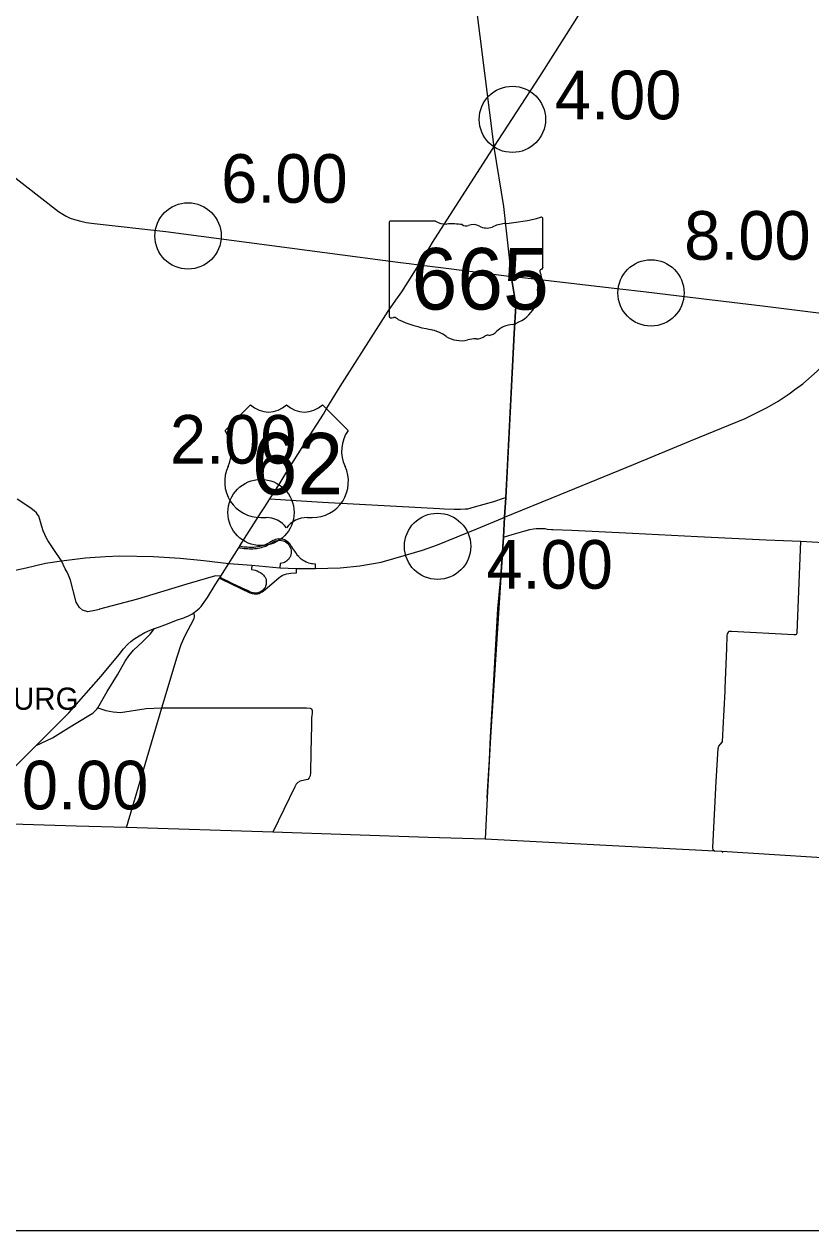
# Model space of a CAD drawing. Extents: x 1659811 to 1934326, y 644115 to 934867.
# Drawn here: x 1783780 to 1801590, y 650175 to 677476 of the extents above; entities that cross this region are included whole.
import ezdxf

# ---------------------------------------------------------------- set-up
doc = ezdxf.new("R2010")
doc.units = 0
for name, color, linetype in [('Default', 7, 'Continuous'), ('GM_X_Corporation_Text', 7, 'Continuous'), ('GM_X_County', 7, 'Continuous'), ('GM_X_County_Road', 7, 'Continuous'), ('GM_X_Interchange_Ramps', 7, 'Continuous'), ('GM_X_Interstate_Route', 7, 'Continuous'), ('GM_X_State_Route', 7, 'Continuous'), ('GM_X_State_Shield', 7, 'Continuous'), ('GM_X_Township', 7, 'Continuous'), ('GM_X_Township_Road', 7, 'Continuous'), ('GM_X_US_Route', 7, 'Continuous'), ('GM_X_US_Shield', 7, 'Continuous'), ('SC_Scratch1', 7, 'Continuous')]:
    doc.layers.add(name, color=color, linetype=linetype)

msp = doc.modelspace()

# ---------------------------------------------------------------- linework, layer by layer
at = {"layer": 'Default'}
for centre in [(1794833, 675322), (1787491, 672684), (1797971, 671396), (1789142, 666427), (1793139, 665662)]:
    msp.add_circle(centre, 750, dxfattribs=at)
at = {"layer": 'GM_X_County'}
msp.add_lwpolyline([(1824608, 657476), (1824149, 657505), (1820365, 657774), (1819565, 657827), (1815551, 657995), (1815251, 658006), (1814713, 658027), (1811039, 658133), (1807036, 658278), (1802918, 658549), (1799575, 658756), (1799409, 658764), (1794213, 659039), (1792928, 659077), (1789408, 659196), (1786100, 659304), (1784956, 659328), (1781576, 659434)], dxfattribs=at)
at = {"layer": 'GM_X_County_Road'}
for points in [[(1784167, 666166), (1784139, 666268), (1784110, 666342), (1784086, 666380), (1784060, 666419), (1784007, 666466), (1783937, 666518), (1783844, 666582), (1783619, 666732)], [(1789344, 666734), (1790537, 666661), (1791789, 666590), (1792769, 666542), (1793180, 666519), (1793295, 666513)], [(1793295, 666513), (1793517, 666503), (1793658, 666499), (1793762, 666507), (1793824, 666510), (1793979, 666556), (1794410, 666679), (1794631, 666749)], [(1794631, 666749), (1794681, 666765)], [(1785488, 664237), (1785482, 664235), (1785415, 664217), (1785225, 664179), (1785099, 664218), (1785031, 664276), (1784960, 664401), (1784830, 664895), (1784787, 665008), (1784751, 665076), (1784708, 665153), (1784623, 665333), (1784452, 665588), (1784319, 665794), (1784282, 665863), (1784251, 665928), (1784214, 666014), (1784184, 666108), (1784167, 666166)], [(1794628, 665869), (1794828, 665926), (1795089, 666006), (1795229, 666043), (1795313, 666060), (1795373, 666064), (1795571, 666063), (1795618, 666051), (1795717, 666046), (1795747, 666045)], [(1795747, 666045), (1796176, 666025), (1797552, 665961), (1799023, 665886), (1800577, 665809), (1801360, 665776), (1801750, 665758), (1801954, 665741), (1802014, 665745), (1802050, 665761), (1802068, 665780), (1802080, 665822), (1802087, 665905)], [(1788230, 664988), (1788111, 664995), (1787461, 664802), (1786344, 664466), (1785488, 664237)], [(1786100, 659304), (1786899, 662007), (1787247, 663159), (1787335, 663439), (1787423, 663644), (1787619, 664011), (1787633, 664034), (1787638, 664068), (1787636, 664100), (1787627, 664132), (1787616, 664155)]]:
    msp.add_lwpolyline(points, dxfattribs=at)
at = {"layer": 'GM_X_Interchange_Ramps'}
for points in [[(1788648, 665645), (1788671, 665631), (1788715, 665621), (1788758, 665616), (1788803, 665612), (1788844, 665609), (1788882, 665608), (1788922, 665607), (1788954, 665607), (1788993, 665609), (1789037, 665614), (1789079, 665620), (1789119, 665628), (1789156, 665637), (1789189, 665647), (1789224, 665659), (1789251, 665669), (1789283, 665685), (1789319, 665704), (1789351, 665720), (1789383, 665737), (1789442, 665769), (1789479, 665786), (1789526, 665797), (1789564, 665799), (1789607, 665796), (1789646, 665786), (1789687, 665769), (1789717, 665749), (1789749, 665723), (1789770, 665698), (1789790, 665668), (1789806, 665637), (1789817, 665605), (1789823, 665573), (1789825, 665540), (1789823, 665505), (1789818, 665476), (1789807, 665441), (1789792, 665410), (1789782, 665393), (1789762, 665367), (1789745, 665348), (1789722, 665329), (1789695, 665311), (1789673, 665299), (1789648, 665290), (1789574, 665271), (1789566, 665173)], [(1790378, 665161), (1790379, 665260), (1790311, 665265), (1790282, 665269), (1790252, 665275), (1790224, 665283), (1790191, 665294), (1790163, 665305), (1790126, 665324), (1790100, 665339), (1790077, 665355), (1790054, 665372), (1790029, 665394), (1790007, 665415), (1789996, 665428), (1789979, 665447), (1789957, 665476), (1789945, 665496), (1789925, 665526), (1789905, 665554), (1789885, 665584), (1789864, 665614), (1789839, 665651), (1789818, 665681), (1789799, 665709), (1789770, 665743), (1789743, 665767), (1789715, 665787), (1789676, 665806), (1789633, 665821), (1789593, 665827), (1789548, 665829), (1789508, 665824), (1789471, 665814), (1789442, 665802), (1789418, 665790), (1789380, 665769), (1789346, 665751), (1789313, 665734), (1789285, 665719), (1789253, 665703), (1789219, 665689), (1789185, 665677), (1789144, 665665), (1789113, 665658), (1789070, 665649), (1789024, 665642), (1788981, 665638), (1788940, 665637), (1788902, 665637), (1788866, 665638), (1788831, 665640), (1788795, 665643), (1788754, 665646), (1788716, 665651), (1788690, 665656), (1788666, 665672)], [(1788202, 664945), (1788246, 664917), (1788890, 664611), (1788940, 664593), (1788986, 664586), (1789026, 664585), (1789063, 664588), (1789100, 664597), (1789125, 664606), (1789168, 664630), (1789233, 664685), (1789547, 664951), (1789583, 664978), (1789623, 665001), (1789655, 665017), (1789680, 665026), (1789716, 665038), (1789771, 665048), (1789819, 665052), (1789947, 665059), (1789948, 665161)], [(1788936, 665236), (1788928, 665136), (1789009, 665119), (1789058, 665104), (1789096, 665087), (1789133, 665066), (1789166, 665041), (1789197, 665012), (1789217, 664990), (1789234, 664966), (1789249, 664931), (1789258, 664897), (1789263, 664860), (1789262, 664827), (1789257, 664795), (1789245, 664759), (1789233, 664734), (1789216, 664706), (1789197, 664683), (1789173, 664660), (1789144, 664640), (1789109, 664622), (1789070, 664611), (1789022, 664605), (1788971, 664608), (1788926, 664619), (1788876, 664641), (1788838, 664659), (1788782, 664685), (1788734, 664708), (1788674, 664737), (1788617, 664764), (1788570, 664786), (1788522, 664809), (1788461, 664838), (1788409, 664863), (1788356, 664888), (1788308, 664911), (1788255, 664936), (1788213, 664962)]]:
    msp.add_lwpolyline(points, dxfattribs=at)
at = {"layer": 'GM_X_Interstate_Route'}
for points in [[(1801226, 669208), (1801405, 669341), (1801729, 669625), (1801864, 669759), (1802106, 670017), (1802426, 670424), (1802697, 670834)], [(1800959, 669021), (1801098, 669113), (1801226, 669208)], [(1794609, 666298), (1794658, 666318), (1795918, 666832), (1797576, 667510), (1798866, 668046), (1800101, 668557), (1800602, 668805), (1800850, 668949), (1800959, 669021)], [(1788411, 665272), (1788936, 665236), (1789566, 665173), (1789948, 665161), (1790378, 665161), (1790931, 665174), (1791380, 665222), (1791866, 665300), (1792438, 665469), (1792800, 665575), (1793140, 665698), (1794026, 666055), (1794609, 666298)], [(1783114, 665027), (1783830, 665175), (1784266, 665280), (1784623, 665333), (1785169, 665398), (1785278, 665407), (1785620, 665431), (1785943, 665448), (1786709, 665435), (1787312, 665395), (1787847, 665340), (1788411, 665272)]]:
    msp.add_lwpolyline(points, dxfattribs=at)
at = {"layer": 'GM_X_State_Route'}
for points in [[(1783535, 674036), (1783804, 673822), (1784562, 673240), (1784654, 673177), (1784734, 673128), (1784820, 673089), (1784919, 673053), (1785066, 673017), (1785185, 672991), (1785368, 672966), (1786989, 672782), (1788878, 672539), (1792298, 672084), (1792500, 672057), (1792717, 672032)], [(1792717, 672032), (1793275, 671961), (1794757, 671777)], [(1794757, 671777), (1794806, 671771), (1797266, 671486), (1797804, 671424), (1799105, 671270), (1800498, 671103), (1801820, 670938), (1801979, 670920)]]:
    msp.add_lwpolyline(points, dxfattribs=at)
at = {"layer": 'GM_X_State_Shield'}
for p, q in [((1792042, 672983), (1792042, 670870)), ((1793095, 673019), (1792076, 673019)), ((1795522, 671966), (1795522, 673072)), ((1795522, 671967), (1795522, 671966))]:
    msp.add_line(p, q, dxfattribs=at)
for centre, major_axis, start_param, end_param in [((1792081, 672988), (40.3, 0), 1.712693, 3.28349), ((1793338, 673265), (391, 0), 4.042523, 4.731795), ((1794282, 675901), (3691, 0), 4.814394, 5.042369), ((1795483, 673076), (38.7, 0), 6.141152, 7.989035), ((1793467, 671833), (1404, 0), 1.404758, 1.657858), ((1793786, 672999), (113, 0), 3.836095, 5.185415), ((1793952, 672754), (235, 0), 0.950623, 2.079405), ((1794255, 673089), (282, 0), 4.081561, 5.145723), ((1794753, 672374), (743, 0), 1.699011, 2.107814), ((1795513, 671885), (60, 0), 1.883978, 3.671073), ((1795481, 671962), (41.5, 0), 5.05454, 6.418171), ((1795661, 671504), (262, 0), 2.387724, 3.262537), ((1795132, 671745), (360, 0), 5.934695, 6.695948), ((1794489, 671363), (923, 0), 5.101752, 6.440018), ((1792082, 670865), (40.7, 0), 3.00124, 4.508301), ((1792088, 671081), (310, 0), 4.665946, 4.897461), ((1792151, 670748), (112, 0), 0.519207, 1.627899), ((1793565, 672647), (2665, 0), 4.195997, 4.488961), ((1792770, 669920), (834, 0), 0.823519, 1.323587), ((1794878, 670277), (506, 0), 1.647645, 2.488434), ((1793672, 670737), (529, 0), 4.026481, 4.996735), ((1793978, 670007), (435, 0), 1.495662, 1.94098), ((1794016, 670579), (282, 0), 4.691044, 5.507374), ((1794271, 670374), (79.4, 0), 1.147584, 2.315152), ((1794238, 670665), (298, 0), 4.937069, 5.64225)]:
    msp.add_ellipse(centre, major_axis=major_axis, ratio=0.8, start_param=start_param, end_param=end_param, dxfattribs=at)
at = {"layer": 'GM_X_Township'}
msp.add_lwpolyline([(1793990, 678050), (1794416, 674693), (1794635, 673347), (1794806, 671771), (1794893, 671228), (1794908, 671097), (1794874, 670478), (1794681, 666765), (1794658, 666318), (1794628, 665869), (1794571, 664962), (1794341, 661348), (1794272, 660115), (1794265, 659967), (1794213, 659039)], dxfattribs=at)
at = {"layer": 'GM_X_Township_Road'}
for points in [[(1794711, 667339), (1794874, 670478), (1794908, 671097), (1794893, 671228), (1794806, 671771)], [(1794628, 665869), (1794658, 666318), (1794681, 666765), (1794711, 667339)], [(1794594, 665324), (1794628, 665869)], [(1799648, 662419), (1799650, 662451), (1799688, 663348), (1799698, 663637), (1799703, 663679), (1799715, 663708), (1799736, 663740), (1799796, 663743), (1801206, 663665), (1801248, 663664), (1801274, 663678), (1801279, 663708), (1801360, 665776)], [(1794312, 660830), (1794341, 661348), (1794413, 662634), (1794505, 664244), (1794571, 664962), (1794594, 665324)], [(1784050, 661158), (1784421, 661328), (1784785, 661553), (1785245, 661832), (1785332, 661887), (1785362, 661915), (1785407, 661955), (1785429, 661979), (1785449, 662005), (1785660, 662374), (1785891, 662758), (1786065, 663060), (1786148, 663185), (1786257, 663311), (1786461, 663499), (1786634, 663678), (1786734, 663801)], [(1799409, 658764), (1799379, 658791), (1799373, 658847), (1799448, 660342), (1799494, 661089), (1799505, 661143), (1799544, 661188), (1799589, 661239), (1799607, 661542), (1799647, 662387), (1799648, 662419)], [(1785449, 662005), (1785631, 661949), (1785794, 661914), (1785961, 661904), (1786544, 661990), (1786899, 662007), (1790170, 662010), (1790258, 661999), (1790282, 661987), (1790304, 661949), (1790304, 661888), (1790293, 661830), (1790285, 661792), (1790284, 661772)], [(1790284, 661772), (1790284, 661736), (1790282, 661618), (1790271, 661003), (1790262, 660542), (1790255, 660466), (1790233, 660426), (1790200, 660384), (1790128, 660371), (1790032, 660347), (1789976, 660322), (1789939, 660284), (1789905, 660222), (1789408, 659196)], [(1794265, 659967), (1794272, 660115), (1794312, 660830)], [(1799600, 658737), (1799575, 658756), (1799409, 658764)]]:
    msp.add_lwpolyline(points, dxfattribs=at)
at = {"layer": 'GM_X_US_Route'}
for points in [[(1794369, 674621), (1794416, 674693), (1795452, 676291), (1796252, 677554), (1796540, 678009)], [(1792717, 672032), (1792863, 672264), (1793021, 672532), (1794369, 674621)], [(1790554, 668655), (1790636, 668785), (1790931, 669274), (1791427, 670046), (1792022, 670984), (1792196, 671234), (1792328, 671423), (1792474, 671646), (1792717, 672032)], [(1788666, 665672), (1789138, 666416), (1789230, 666553), (1789344, 666734), (1789553, 667059), (1789715, 667323), (1790257, 668184), (1790554, 668655)], [(1788490, 665396), (1788648, 665645), (1788666, 665672)], [(1788171, 664896), (1788202, 664945), (1788213, 664962), (1788230, 664988), (1788411, 665272), (1788490, 665396)], [(1787043, 663919), (1787255, 663998), (1787392, 664047), (1787427, 664059), (1787486, 664082), (1787528, 664103), (1787574, 664128), (1787616, 664155), (1787658, 664184), (1787715, 664230), (1787748, 664259), (1787789, 664303), (1787821, 664347), (1787928, 664501), (1788104, 664792), (1788171, 664896)], [(1782818, 659962), (1782858, 659989), (1782950, 660058), (1783174, 660262), (1783295, 660401), (1784050, 661158), (1784789, 661898), (1785521, 662721), (1785931, 663218), (1786031, 663343), (1786129, 663449), (1786199, 663506), (1786267, 663559), (1786382, 663639), (1786511, 663709), (1786630, 663762), (1786734, 663801), (1786844, 663844), (1787022, 663911), (1787043, 663919)]]:
    msp.add_lwpolyline(points, dxfattribs=at)
at = {"layer": 'GM_X_US_Shield'}
for p, q in [((1788908, 668865), (1788328, 668285)), ((1791112, 668285), (1790532, 668865)), ((1789140, 666313), (1789256, 666313)), ((1790184, 666313), (1790300, 666313))]:
    msp.add_line(p, q, dxfattribs=at)
for centre, radius, start, end in [((1789314, 669280), 580, 225.573, 314.427), ((1790126, 669280), 580, 225.573, 314.427), ((1787663, 667819), 812, 334.5471, 35.0009), ((1791778, 667819), 812, 144.9991, 205.4529), ((1789131, 667125), 812, 154.8319, 270.6383), ((1790309, 667125), 812, 269.3617, 25.1681), ((1789256, 665733), 580, 36.8699, 90), ((1790184, 665733), 580, 90, 143.1301)]:
    msp.add_arc(centre, radius, start, end, dxfattribs=at)
at = {"layer": 'SC_Scratch1'}
msp.add_lwpolyline([(1730291, 784675), (1926541, 784675), (1926541, 650175), (1730291, 650175)], close=True, dxfattribs=at)

# ---------------------------------------------------------------- texts
at = {"layer": 'Default'}
for s, p in [('4.00', (1795796, 675324)), ('6.00', (1788241, 673434)), ('8.00', (1798721, 672146)), ('2.00', (1787081, 667533)), ('4.00', (1794245, 664703)), ('0.00', (1783730, 659710))]:
    msp.add_text(s, height=1100, dxfattribs=at).set_placement(p)
at = {"layer": 'GM_X_Corporation_Text'}
msp.add_text('HARRISBURG', height=500, rotation=0, dxfattribs=at).set_placement((1780555, 661965))
at = {"layer": 'GM_X_State_Shield'}
msp.add_text('665', height=1392.2, dxfattribs=at).set_placement((1792552, 671019))
at = {"layer": 'GM_X_US_Shield'}
msp.add_text('62', height=1392.2, dxfattribs=at).set_placement((1788932, 666835))

doc.saveas('drawing.dxf')
